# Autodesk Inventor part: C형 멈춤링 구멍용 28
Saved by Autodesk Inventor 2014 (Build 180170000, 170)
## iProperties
Created: 2026-08
Part Number: C형 멈춤링 구멍용 28
Material: 일반
Document SubType Name: Modeling
Designer: dg
Density: 1 g/cm^3
Appearance: 기본값
Author: dg
Author: jhkim
Description: 리테이닝 링(C형)
Creation Date: 2026-07-31
Sending System: Autodesk Inventor 2027
Preprocessor: ST-DEVELOPER v20.1
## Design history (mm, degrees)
node "C형 멈춤링 구멍용 281"
body "Solid1"
node "기준1"
